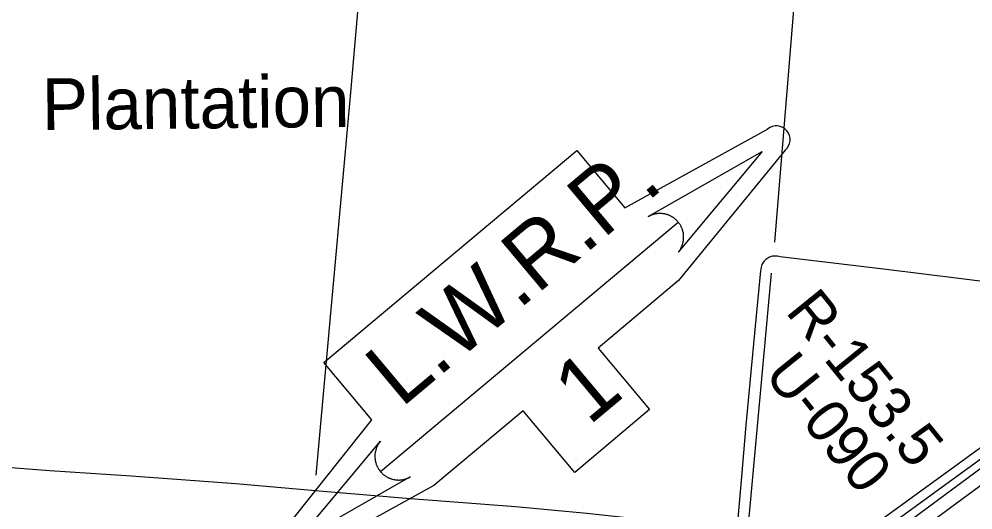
# Model space of a CAD drawing. Extents: x 3445503 to 3483459, y 540493 to 566012.
# Drawn here: x 3450977 to 3452821, y 550370 to 551320 of the extents above; entities that cross this region are included whole.
import ezdxf

# ---------------------------------------------------------------- set-up
doc = ezdxf.new("R2010")
doc.units = 0
for name, color, linetype in [('V-BLDG-IDEN', 7, 'Continuous'), ('V-DTCH-CNTR', 7, 'Continuous'), ('V-LEVE-TOET', 7, 'Continuous'), ('V-RIVR-RANG-IDEN', 7, 'Continuous'), ('V-ROAD-CNTR', 7, 'Continuous'), ('V-TOPO-SHOR', 7, 'Continuous'), ('V-TOPO-WATR-IDEN', 7, 'Continuous')]:
    doc.layers.add(name, color=color, linetype=linetype)

msp = doc.modelspace()

# ---------------------------------------------------------------- linework, layer by layer
at = {"layer": 'V-DTCH-CNTR'}
for points in [[(3453342.9, 550875.9), (3453098.5, 550695.1), (3452833.1, 550488.9), (3452569.8, 550297.4), (3452355.1, 550138.3)], [(3452448.4, 550859.9), (3452446.1, 550860.6), (3452443.6, 550861.1), (3452441.2, 550861.4), (3452438.7, 550861.5), (3452436.2, 550861.4), (3452433.8, 550861), (3452431.4, 550860.4), (3452429, 550859.7), (3452426.8, 550858.7), (3452424.6, 550857.5), (3452422.5, 550856.2), (3452420.6, 550854.6), (3452418.8, 550852.9), (3452417.1, 550851.1), (3452415.7, 550849.1), (3452414.4, 550847), (3452413.3, 550844.8), (3452412.4, 550842.5), (3452411.7, 550840.1), (3452411.2, 550837.7), (3452410.9, 550835.2), (3452410.8, 550832.8)], [(3453032.1, 550792.9), (3452872, 550808.3), (3452653.8, 550835.6), (3452448.4, 550859.9)], [(3452410.8, 550832.8), (3452400.2, 550725.8), (3452382.4, 550534.6), (3452373.1, 550427.3), (3452364.9, 550332.1), (3452359.3, 550250.6), (3452355.1, 550138.3)], [(3450860.2, 550460.1), (3451036.4, 550447), (3451193.8, 550436.4), (3451396.4, 550421.6), (3451557, 550407.1), (3451733.7, 550392.4), (3451936.6, 550376.9), (3452074.6, 550364.4), (3452246.1, 550345.2), (3452364.9, 550332.1)]]:
    msp.add_lwpolyline(points, dxfattribs=at)
at = {"layer": 'V-LEVE-TOET'}
msp.add_lwpolyline([(3452946.3, 550498.3), (3452789.9, 550383.7), (3452601.6, 550243.6), (3452413.3, 550102.4), (3452211, 549956.6), (3452005.4, 549805.7), (3451824.6, 549667.4), (3451660.3, 549546.8), (3451635, 549525.3), (3451602.2, 549493.8), (3451576, 549459.4), (3451487.5, 549313.9), (3451418.6, 549196.8), (3451396.4, 549169.1), (3451367.1, 549134.7), (3451284.2, 549052.5), (3451198.2, 548960.9), (3451057.3, 548808.2), (3450924.9, 548670), (3450798.1, 548533.9), (3450638.8, 548368.3), (3450580, 548310.5), (3450564.1, 548297.4)], dxfattribs=at)
at = {"layer": 'V-ROAD-CNTR'}
msp.add_lwpolyline([(3453695.9, 551080.7), (3453195.7, 550716.2), (3452564.8, 550249.6), (3452094, 549907.5), (3451781.4, 549679.3), (3451700, 549618.8)], dxfattribs=at)
at = {"layer": 'V-TOPO-SHOR'}
for p, q in [((3452438.6, 550888.6), (3452512.6, 551803.5)), ((3452371.4, 550168.8), (3452431.9, 550828.1))]:
    msp.add_line(p, q, dxfattribs=at)
for points in [[(3451678.5, 551877.5), (3451617.9, 551177.9), (3451550.7, 550437.9)], [(3451137.6, 548975), (3451281.6, 549106), (3451375.8, 549213.6), (3451456.5, 549361.6), (3451490.1, 549449.1), (3451584.3, 549550), (3451880.3, 549772), (3452135.9, 549960.3), (3453292.9, 550801.2), (3453326.6, 550834.8), (3453313.1, 550902.1)]]:
    msp.add_lwpolyline(points, dxfattribs=at)
at = {"layer": 'V-TOPO-WATR-IDEN'}
msp.add_line((3451675.7, 550444.7), (3452251.4, 550927.3), dxfattribs=at)
for points in [[(3451468.7, 550305.7), (3451659.1, 550544.5), (3451566.1, 550655.4), (3452055.4, 551065.7), (3452148.4, 550954.8), (3452424.3, 551107)], [(3452458.4, 551066.3), (3452252.3, 550814.3), (3452096.4, 550683.6), (3452196.2, 550564.6), (3452051.4, 550443.1), (3451951.6, 550562.1), (3451779.3, 550417.7), (3451502.7, 550265)]]:
    msp.add_lwpolyline(points, dxfattribs=at)
for points in [[(3452193.7, 550937.7), (3452414.1, 551063.8), (3452251.5, 550868.8), (3452254.3, 550872.4), (3452256.5, 550876.2), (3452257.4, 550877.8), (3452258, 550879.2), (3452258.8, 550880.9), (3452259.4, 550882.6), (3452259.9, 550884.1), (3452260.5, 550886.2), (3452261.1, 550888.5), (3452261.3, 550889.8), (3452261.6, 550891.4), (3452261.8, 550893.6), (3452262, 550895.3), (3452262, 550897.2), (3452262, 550898.4), (3452262, 550899.8), (3452261.9, 550901.4), (3452261.8, 550902.9), (3452261.6, 550904.4), (3452261.4, 550905.6), (3452261.1, 550907.4), (3452260.7, 550909.1), (3452260.3, 550910.5), (3452259.8, 550912), (3452259.4, 550913.4), (3452258.9, 550914.6), (3452258.5, 550915.5), (3452257.9, 550916.9), (3452257.3, 550918.3), (3452256.6, 550919.6), (3452255.9, 550920.9), (3452255.2, 550922.1), (3452254.3, 550923.3), (3452253.6, 550924.4), (3452252.6, 550925.8), (3452251.4, 550927.3), (3452250.9, 550927.8), (3452250.3, 550928.5), (3452249.6, 550929.3), (3452248.8, 550930.1), (3452248.1, 550930.8), (3452247.4, 550931.5), (3452246.5, 550932.3), (3452245.9, 550932.9), (3452244.9, 550933.6), (3452244, 550934.3), (3452243.4, 550934.8), (3452241.8, 550936), (3452240.8, 550936.5), (3452240.2, 550936.9), (3452239.2, 550937.6), (3452238.2, 550938.1), (3452237.2, 550938.6), (3452236, 550939.2), (3452234.9, 550939.8), (3452234, 550940.2), (3452233.2, 550940.5), (3452232.1, 550940.9), (3452231.1, 550941.2), (3452230, 550941.6), (3452228.8, 550941.9), (3452227.7, 550942.3), (3452226.2, 550942.6), (3452225.1, 550942.8), (3452223.9, 550943.1), (3452222.7, 550943.2), (3452221.7, 550943.4), (3452220.7, 550943.5), (3452219.1, 550943.6), (3452219, 550943.6), (3452218.1, 550943.7), (3452217.4, 550943.7), (3452216.4, 550943.7), (3452215.1, 550943.7), (3452214.1, 550943.6), (3452213.1, 550943.6), (3452212, 550943.5), (3452210.8, 550943.4), (3452210, 550943.3), (3452209, 550943.1), (3452207.5, 550942.8), (3452206.7, 550942.7), (3452206, 550942.5), (3452205.4, 550942.4), (3452204.7, 550942.2), (3452203.8, 550941.9), (3452202.8, 550941.7), (3452201.9, 550941.4), (3452201, 550941.1), (3452199.8, 550940.6), (3452199.1, 550940.3), (3452198, 550939.9), (3452196.8, 550939.3), (3452195.8, 550938.9), (3452195.1, 550938.5), (3452194.5, 550938.2), (3452194, 550937.9)], [(3451733.4, 550434.3), (3451513, 550308.2), (3451675.6, 550503.3), (3451672.8, 550499.6), (3451670.5, 550495.8), (3451669.7, 550494.3), (3451669.1, 550492.8), (3451668.3, 550491.1), (3451667.7, 550489.4), (3451667.2, 550487.9), (3451666.6, 550485.8), (3451666, 550483.5), (3451665.8, 550482.3), (3451665.5, 550480.6), (3451665.2, 550478.4), (3451665.1, 550476.7), (3451665, 550474.8), (3451665, 550473.6), (3451665.1, 550472.3), (3451665.2, 550470.6), (3451665.3, 550469.1), (3451665.5, 550467.6), (3451665.7, 550466.4), (3451666, 550464.6), (3451666.4, 550462.9), (3451666.8, 550461.6), (3451667.3, 550460), (3451667.7, 550458.6), (3451668.2, 550457.4), (3451668.5, 550456.5), (3451669.1, 550455.1), (3451669.8, 550453.7), (3451670.5, 550452.4), (3451671.2, 550451.1), (3451671.9, 550449.9), (3451672.7, 550448.7), (3451673.4, 550447.7), (3451674.5, 550446.2), (3451675.7, 550444.7), (3451676.1, 550444.2), (3451676.8, 550443.5), (3451677.5, 550442.7), (3451678.2, 550441.9), (3451679, 550441.2), (3451679.7, 550440.5), (3451680.6, 550439.7), (3451681.2, 550439.2), (3451682.2, 550438.4), (3451683.1, 550437.7), (3451683.7, 550437.2), (3451685.3, 550436.1), (3451686.2, 550435.5), (3451686.9, 550435.1), (3451687.9, 550434.5), (3451688.9, 550433.9), (3451689.9, 550433.4), (3451691.1, 550432.8), (3451692.2, 550432.3), (3451693.1, 550431.9), (3451693.9, 550431.6), (3451695, 550431.1), (3451695.9, 550430.8), (3451697.1, 550430.4), (3451698.2, 550430.1), (3451699.4, 550429.8), (3451700.9, 550429.4), (3451702, 550429.2), (3451703.2, 550429), (3451704.4, 550428.8), (3451705.4, 550428.6), (3451706.4, 550428.5), (3451708, 550428.4), (3451708.1, 550428.4), (3451709, 550428.4), (3451709.7, 550428.3), (3451710.7, 550428.3), (3451712, 550428.3), (3451713, 550428.4), (3451713.9, 550428.4), (3451715.1, 550428.5), (3451716.2, 550428.7), (3451717, 550428.8), (3451718.1, 550428.9), (3451719.5, 550429.2), (3451720.4, 550429.3), (3451721, 550429.5), (3451721.7, 550429.6), (3451722.4, 550429.8), (3451723.3, 550430.1), (3451724.3, 550430.4), (3451725.2, 550430.7), (3451726.1, 550431), (3451727.3, 550431.4), (3451728, 550431.7), (3451729.1, 550432.1), (3451730.3, 550432.7), (3451731.3, 550433.2), (3451732, 550433.5), (3451732.6, 550433.9), (3451733.1, 550434.1)]]:
    msp.add_lwpolyline(points, close=True, dxfattribs=at)
msp.add_arc((3452441.4, 551086.7), 26.5, 309.9794, 129.9794, dxfattribs=at)

# ---------------------------------------------------------------- texts
at = {"layer": 'V-BLDG-IDEN'}
msp.add_text('Plantation', height=100, rotation=0.6418, dxfattribs=at).set_placement((3451021.7, 551104.8))
at = {"layer": 'V-RIVR-RANG-IDEN'}
for s, rotation, p in [('R-153.5', 308.9735, (3452457.3, 550753.3)), ('U-090', 308.7328, (3452415.7, 550631.9))]:
    msp.add_text(s, height=83, rotation=rotation, dxfattribs=at).set_placement(p)
at = {"layer": 'V-TOPO-WATR-IDEN'}
for s, rotation, p in [('L.W.R.P.', 39.9793, (3451716, 550566.5)), ('1', 39.9794, (3452078.8, 550532.1))]:
    msp.add_text(s, height=124.5, rotation=rotation, dxfattribs=at).set_placement(p)

doc.saveas('drawing.dxf')
